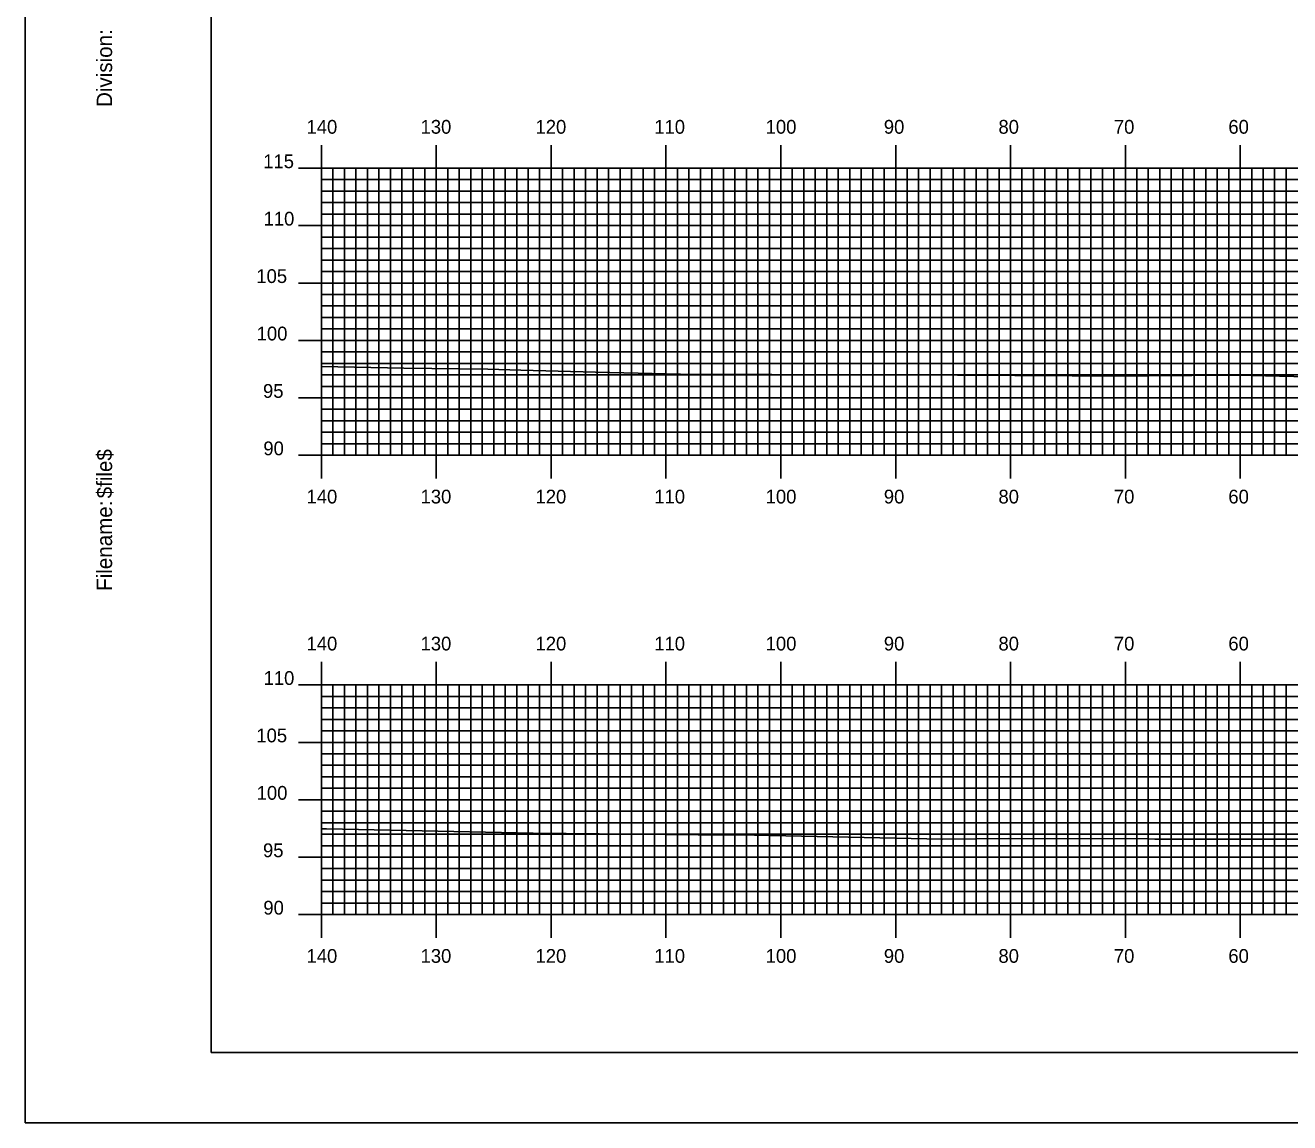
# Model space of a CAD drawing. Extents: x 1764939 to 1765282, y 442591 to 442811.
# Drawn here: x 1764939.1 to 1765049.2, y 442590.5 to 442686.1 of the extents above; entities that cross this region are included whole.
import ezdxf

# ---------------------------------------------------------------- set-up
doc = ezdxf.new("R2010")
doc.units = 0
for name, color, linetype in [('BORDER', 7, 'Continuous'), ('H_V ANNOTATION', 7, 'Continuous'), ('MAJOR', 7, 'Continuous'), ('MINOR', 7, 'Continuous'), ('PLOT BOUNDARY', 7, 'Continuous'), ('S_Roadway_Centerline', 7, 'Continuous')]:
    doc.layers.add(name, color=color, linetype=linetype)

msp = doc.modelspace()

# ---------------------------------------------------------------- linework, layer by layer
at = {"layer": 'BORDER'}
msp.add_lwpolyline([(1764955.26, 442596.67), (1765275.26, 442596.67), (1765275.26, 442806.67), (1764955.26, 442806.67)], close=True, dxfattribs=at)
at = {"layer": 'MAJOR'}
for p, q in [((1764964.86, 442675.67), (1764964.86, 442673.67)), ((1764974.86, 442675.67), (1764974.86, 442673.67)), ((1764984.86, 442675.67), (1764984.86, 442673.67)), ((1764994.86, 442675.67), (1764994.86, 442673.67)), ((1765004.86, 442675.67), (1765004.86, 442673.67)), ((1765014.86, 442675.67), (1765014.86, 442673.67)), ((1765024.86, 442675.67), (1765024.86, 442673.67)), ((1765034.86, 442675.67), (1765034.86, 442673.67)), ((1765044.86, 442675.67), (1765044.86, 442673.67)), ((1764962.85, 442673.67), (1764964.86, 442673.67)), ((1764964.86, 442673.67), (1765244.86, 442673.67)), ((1764964.86, 442648.67), (1764964.86, 442673.67)), ((1764964.86, 442648.67), (1764964.86, 442673.67)), ((1764964.86, 442673.67), (1765244.86, 442673.67)), ((1764974.86, 442648.67), (1764974.86, 442673.67)), ((1764984.86, 442648.67), (1764984.86, 442673.67)), ((1764994.86, 442648.67), (1764994.86, 442673.67)), ((1765004.86, 442648.67), (1765004.86, 442673.67)), ((1765014.86, 442648.67), (1765014.86, 442673.67)), ((1765024.86, 442648.67), (1765024.86, 442673.67)), ((1765034.86, 442648.67), (1765034.86, 442673.67)), ((1765044.86, 442648.67), (1765044.86, 442673.67)), ((1764962.85, 442668.67), (1764964.86, 442668.67)), ((1764964.86, 442668.67), (1765244.86, 442668.67)), ((1764962.85, 442663.67), (1764964.86, 442663.67)), ((1764964.86, 442663.67), (1765244.86, 442663.67)), ((1764962.85, 442658.67), (1764964.86, 442658.67)), ((1764964.86, 442658.67), (1765244.86, 442658.67)), ((1764962.85, 442653.67), (1764964.86, 442653.67)), ((1764964.86, 442653.67), (1765244.86, 442653.67)), ((1764962.85, 442648.67), (1764964.86, 442648.67)), ((1764964.86, 442648.67), (1765244.86, 442648.67)), ((1764964.86, 442648.67), (1765244.86, 442648.67)), ((1764964.86, 442646.66), (1764964.86, 442648.67)), ((1764974.86, 442646.66), (1764974.86, 442648.67)), ((1764984.86, 442646.66), (1764984.86, 442648.67)), ((1764994.86, 442646.66), (1764994.86, 442648.67)), ((1765004.86, 442646.66), (1765004.86, 442648.67)), ((1765014.86, 442646.66), (1765014.86, 442648.67)), ((1765024.86, 442646.66), (1765024.86, 442648.67)), ((1765034.86, 442646.66), (1765034.86, 442648.67)), ((1765044.86, 442646.66), (1765044.86, 442648.67)), ((1764964.86, 442630.67), (1764964.86, 442628.67)), ((1764974.86, 442630.67), (1764974.86, 442628.67)), ((1764984.86, 442630.67), (1764984.86, 442628.67)), ((1764994.86, 442630.67), (1764994.86, 442628.67)), ((1765004.86, 442630.67), (1765004.86, 442628.67)), ((1765014.86, 442630.67), (1765014.86, 442628.67)), ((1765024.86, 442630.67), (1765024.86, 442628.67)), ((1765034.86, 442630.67), (1765034.86, 442628.67)), ((1765044.86, 442630.67), (1765044.86, 442628.67)), ((1764962.85, 442628.67), (1764964.86, 442628.67)), ((1764964.86, 442628.67), (1765244.86, 442628.67)), ((1764964.86, 442608.67), (1764964.86, 442628.67)), ((1764964.86, 442608.67), (1764964.86, 442628.67)), ((1764964.86, 442628.67), (1765244.86, 442628.67)), ((1764974.86, 442608.67), (1764974.86, 442628.67)), ((1764984.86, 442608.67), (1764984.86, 442628.67)), ((1764994.86, 442608.67), (1764994.86, 442628.67)), ((1765004.86, 442608.67), (1765004.86, 442628.67)), ((1765014.86, 442608.67), (1765014.86, 442628.67)), ((1765024.86, 442608.67), (1765024.86, 442628.67)), ((1765034.86, 442608.67), (1765034.86, 442628.67)), ((1765044.86, 442608.67), (1765044.86, 442628.67)), ((1764962.85, 442623.67), (1764964.86, 442623.67)), ((1764964.86, 442623.67), (1765244.86, 442623.67)), ((1764962.85, 442618.67), (1764964.86, 442618.67)), ((1764964.86, 442618.67), (1765244.86, 442618.67)), ((1764962.85, 442613.67), (1764964.86, 442613.67)), ((1764964.86, 442613.67), (1765244.86, 442613.67)), ((1764962.85, 442608.67), (1764964.86, 442608.67)), ((1764964.86, 442608.67), (1765244.86, 442608.67)), ((1764964.86, 442608.67), (1765244.86, 442608.67)), ((1764964.86, 442606.66), (1764964.86, 442608.67)), ((1764974.86, 442606.66), (1764974.86, 442608.67)), ((1764984.86, 442606.66), (1764984.86, 442608.67)), ((1764994.86, 442606.66), (1764994.86, 442608.67)), ((1765004.86, 442606.66), (1765004.86, 442608.67)), ((1765014.86, 442606.66), (1765014.86, 442608.67)), ((1765024.86, 442606.66), (1765024.86, 442608.67)), ((1765034.86, 442606.66), (1765034.86, 442608.67)), ((1765044.86, 442606.66), (1765044.86, 442608.67))]:
    msp.add_line(p, q, dxfattribs=at)
at = {"layer": 'MINOR'}
for p, q in [((1764964.86, 442672.67), (1765244.86, 442672.67)), ((1764964.86, 442672.67), (1764966.86, 442672.67)), ((1764965.86, 442648.67), (1764965.86, 442673.67)), ((1764966.86, 442648.67), (1764966.86, 442673.67)), ((1764967.86, 442648.67), (1764967.86, 442673.67)), ((1764968.86, 442648.67), (1764968.86, 442673.67)), ((1764969.86, 442648.67), (1764969.86, 442673.67)), ((1764970.86, 442648.67), (1764970.86, 442673.67)), ((1764971.86, 442648.67), (1764971.86, 442673.67)), ((1764972.86, 442648.67), (1764972.86, 442673.67)), ((1764973.86, 442648.67), (1764973.86, 442673.67)), ((1764975.86, 442648.67), (1764975.86, 442673.67)), ((1764976.86, 442648.67), (1764976.86, 442673.67)), ((1764977.86, 442648.67), (1764977.86, 442673.67)), ((1764978.86, 442648.67), (1764978.86, 442673.67)), ((1764979.86, 442648.67), (1764979.86, 442673.67)), ((1764980.86, 442648.67), (1764980.86, 442673.67)), ((1764981.86, 442648.67), (1764981.86, 442673.67)), ((1764982.86, 442648.67), (1764982.86, 442673.67)), ((1764983.86, 442648.67), (1764983.86, 442673.67)), ((1764985.86, 442648.67), (1764985.86, 442673.67)), ((1764986.86, 442648.67), (1764986.86, 442673.67)), ((1764987.86, 442648.67), (1764987.86, 442673.67)), ((1764988.86, 442648.67), (1764988.86, 442673.67)), ((1764989.86, 442648.67), (1764989.86, 442673.67)), ((1764990.86, 442648.67), (1764990.86, 442673.67)), ((1764991.86, 442648.67), (1764991.86, 442673.67)), ((1764992.86, 442648.67), (1764992.86, 442673.67)), ((1764993.86, 442648.67), (1764993.86, 442673.67)), ((1764995.86, 442648.67), (1764995.86, 442673.67)), ((1764996.86, 442648.67), (1764996.86, 442673.67)), ((1764997.86, 442648.67), (1764997.86, 442673.67)), ((1764998.86, 442648.67), (1764998.86, 442673.67)), ((1764999.86, 442648.67), (1764999.86, 442673.67)), ((1765000.86, 442648.67), (1765000.86, 442673.67)), ((1765001.86, 442648.67), (1765001.86, 442673.67)), ((1765002.86, 442648.67), (1765002.86, 442673.67)), ((1765003.86, 442648.67), (1765003.86, 442673.67)), ((1765005.86, 442648.67), (1765005.86, 442673.67)), ((1765006.86, 442648.67), (1765006.86, 442673.67)), ((1765007.86, 442648.67), (1765007.86, 442673.67)), ((1765008.86, 442648.67), (1765008.86, 442673.67)), ((1765009.86, 442648.67), (1765009.86, 442673.67)), ((1765010.86, 442648.67), (1765010.86, 442673.67)), ((1765011.86, 442648.67), (1765011.86, 442673.67)), ((1765012.86, 442648.67), (1765012.86, 442673.67)), ((1765013.86, 442648.67), (1765013.86, 442673.67)), ((1765015.86, 442648.67), (1765015.86, 442673.67)), ((1765016.86, 442648.67), (1765016.86, 442673.67)), ((1765017.86, 442648.67), (1765017.86, 442673.67)), ((1765018.86, 442648.67), (1765018.86, 442673.67)), ((1765019.86, 442648.67), (1765019.86, 442673.67)), ((1765020.86, 442648.67), (1765020.86, 442673.67)), ((1765021.86, 442648.67), (1765021.86, 442673.67)), ((1765022.86, 442648.67), (1765022.86, 442673.67)), ((1765023.86, 442648.67), (1765023.86, 442673.67)), ((1765025.86, 442648.67), (1765025.86, 442673.67)), ((1765026.86, 442648.67), (1765026.86, 442673.67)), ((1765027.86, 442648.67), (1765027.86, 442673.67)), ((1765028.86, 442648.67), (1765028.86, 442673.67)), ((1765029.86, 442648.67), (1765029.86, 442673.67)), ((1765030.86, 442648.67), (1765030.86, 442673.67)), ((1765031.86, 442648.67), (1765031.86, 442673.67)), ((1765032.86, 442648.67), (1765032.86, 442673.67)), ((1765033.86, 442648.67), (1765033.86, 442673.67)), ((1765035.86, 442648.67), (1765035.86, 442673.67)), ((1765036.86, 442648.67), (1765036.86, 442673.67)), ((1765037.86, 442648.67), (1765037.86, 442673.67)), ((1765038.86, 442648.67), (1765038.86, 442673.67)), ((1765039.86, 442648.67), (1765039.86, 442673.67)), ((1765040.86, 442648.67), (1765040.86, 442673.67)), ((1765041.86, 442648.67), (1765041.86, 442673.67)), ((1765042.86, 442648.67), (1765042.86, 442673.67)), ((1765043.86, 442648.67), (1765043.86, 442673.67)), ((1765045.86, 442648.67), (1765045.86, 442673.67)), ((1765046.86, 442648.67), (1765046.86, 442673.67)), ((1765047.86, 442648.67), (1765047.86, 442673.67)), ((1765048.86, 442648.67), (1765048.86, 442673.67)), ((1764964.86, 442671.67), (1765244.86, 442671.67)), ((1764964.86, 442671.67), (1764966.86, 442671.67)), ((1764964.86, 442670.67), (1765244.86, 442670.67)), ((1764964.86, 442670.67), (1764966.86, 442670.67)), ((1764964.86, 442669.67), (1765244.86, 442669.67)), ((1764964.86, 442669.67), (1764966.86, 442669.67)), ((1764964.86, 442667.67), (1765244.86, 442667.67)), ((1764964.86, 442667.67), (1764966.86, 442667.67)), ((1764964.86, 442666.67), (1765244.86, 442666.67)), ((1764964.86, 442666.67), (1764966.86, 442666.67)), ((1764964.86, 442665.67), (1765244.86, 442665.67)), ((1764964.86, 442665.67), (1764966.86, 442665.67)), ((1764964.86, 442664.67), (1765244.86, 442664.67)), ((1764964.86, 442664.67), (1764966.86, 442664.67)), ((1764964.86, 442662.67), (1765244.86, 442662.67)), ((1764964.86, 442662.67), (1764966.86, 442662.67)), ((1764964.86, 442661.67), (1765244.86, 442661.67)), ((1764964.86, 442661.67), (1764966.86, 442661.67)), ((1764964.86, 442660.67), (1765244.86, 442660.67)), ((1764964.86, 442660.67), (1764966.86, 442660.67)), ((1764964.86, 442659.67), (1765244.86, 442659.67)), ((1764964.86, 442659.67), (1764966.86, 442659.67)), ((1764964.86, 442657.67), (1765244.86, 442657.67)), ((1764964.86, 442657.67), (1764966.86, 442657.67)), ((1764964.86, 442656.67), (1765244.86, 442656.67)), ((1764964.86, 442656.67), (1764966.86, 442656.67)), ((1764964.86, 442655.67), (1765244.86, 442655.67)), ((1764964.86, 442655.67), (1764966.86, 442655.67)), ((1764964.86, 442654.67), (1765244.86, 442654.67)), ((1764964.86, 442654.67), (1764966.86, 442654.67)), ((1764964.86, 442652.67), (1765244.86, 442652.67)), ((1764964.86, 442652.67), (1764966.86, 442652.67)), ((1764964.86, 442651.67), (1765244.86, 442651.67)), ((1764964.86, 442651.67), (1764966.86, 442651.67)), ((1764964.86, 442650.67), (1765244.86, 442650.67)), ((1764964.86, 442650.67), (1764966.86, 442650.67)), ((1764964.86, 442649.67), (1765244.86, 442649.67)), ((1764964.86, 442649.67), (1764966.86, 442649.67)), ((1764965.86, 442608.67), (1764965.86, 442628.67)), ((1764966.86, 442608.67), (1764966.86, 442628.67)), ((1764967.86, 442608.67), (1764967.86, 442628.67)), ((1764968.86, 442608.67), (1764968.86, 442628.67)), ((1764969.86, 442608.67), (1764969.86, 442628.67)), ((1764970.86, 442608.67), (1764970.86, 442628.67)), ((1764971.86, 442608.67), (1764971.86, 442628.67)), ((1764972.86, 442608.67), (1764972.86, 442628.67)), ((1764973.86, 442608.67), (1764973.86, 442628.67)), ((1764975.86, 442608.67), (1764975.86, 442628.67)), ((1764976.86, 442608.67), (1764976.86, 442628.67)), ((1764977.86, 442608.67), (1764977.86, 442628.67)), ((1764978.86, 442608.67), (1764978.86, 442628.67)), ((1764979.86, 442608.67), (1764979.86, 442628.67)), ((1764980.86, 442608.67), (1764980.86, 442628.67)), ((1764981.86, 442608.67), (1764981.86, 442628.67)), ((1764982.86, 442608.67), (1764982.86, 442628.67)), ((1764983.86, 442608.67), (1764983.86, 442628.67)), ((1764985.86, 442608.67), (1764985.86, 442628.67)), ((1764986.86, 442608.67), (1764986.86, 442628.67)), ((1764987.86, 442608.67), (1764987.86, 442628.67)), ((1764988.86, 442608.67), (1764988.86, 442628.67)), ((1764989.86, 442608.67), (1764989.86, 442628.67)), ((1764990.86, 442608.67), (1764990.86, 442628.67)), ((1764991.86, 442608.67), (1764991.86, 442628.67)), ((1764992.86, 442608.67), (1764992.86, 442628.67)), ((1764993.86, 442608.67), (1764993.86, 442628.67)), ((1764995.86, 442608.67), (1764995.86, 442628.67)), ((1764996.86, 442608.67), (1764996.86, 442628.67)), ((1764997.86, 442608.67), (1764997.86, 442628.67)), ((1764998.86, 442608.67), (1764998.86, 442628.67)), ((1764999.86, 442608.67), (1764999.86, 442628.67)), ((1765000.86, 442608.67), (1765000.86, 442628.67)), ((1765001.86, 442608.67), (1765001.86, 442628.67)), ((1765002.86, 442608.67), (1765002.86, 442628.67)), ((1765003.86, 442608.67), (1765003.86, 442628.67)), ((1765005.86, 442608.67), (1765005.86, 442628.67)), ((1765006.86, 442608.67), (1765006.86, 442628.67)), ((1765007.86, 442608.67), (1765007.86, 442628.67)), ((1765008.86, 442608.67), (1765008.86, 442628.67)), ((1765009.86, 442608.67), (1765009.86, 442628.67)), ((1765010.86, 442608.67), (1765010.86, 442628.67)), ((1765011.86, 442608.67), (1765011.86, 442628.67)), ((1765012.86, 442608.67), (1765012.86, 442628.67)), ((1765013.86, 442608.67), (1765013.86, 442628.67)), ((1765015.86, 442608.67), (1765015.86, 442628.67)), ((1765016.86, 442608.67), (1765016.86, 442628.67)), ((1765017.86, 442608.67), (1765017.86, 442628.67)), ((1765018.86, 442608.67), (1765018.86, 442628.67)), ((1765019.86, 442608.67), (1765019.86, 442628.67)), ((1765020.86, 442608.67), (1765020.86, 442628.67)), ((1765021.86, 442608.67), (1765021.86, 442628.67)), ((1765022.86, 442608.67), (1765022.86, 442628.67)), ((1765023.86, 442608.67), (1765023.86, 442628.67)), ((1765025.86, 442608.67), (1765025.86, 442628.67)), ((1765026.86, 442608.67), (1765026.86, 442628.67)), ((1765027.86, 442608.67), (1765027.86, 442628.67)), ((1765028.86, 442608.67), (1765028.86, 442628.67)), ((1765029.86, 442608.67), (1765029.86, 442628.67)), ((1765030.86, 442608.67), (1765030.86, 442628.67)), ((1765031.86, 442608.67), (1765031.86, 442628.67)), ((1765032.86, 442608.67), (1765032.86, 442628.67)), ((1765033.86, 442608.67), (1765033.86, 442628.67)), ((1765035.86, 442608.67), (1765035.86, 442628.67)), ((1765036.86, 442608.67), (1765036.86, 442628.67)), ((1765037.86, 442608.67), (1765037.86, 442628.67)), ((1765038.86, 442608.67), (1765038.86, 442628.67)), ((1765039.86, 442608.67), (1765039.86, 442628.67)), ((1765040.86, 442608.67), (1765040.86, 442628.67)), ((1765041.86, 442608.67), (1765041.86, 442628.67)), ((1765042.86, 442608.67), (1765042.86, 442628.67)), ((1765043.86, 442608.67), (1765043.86, 442628.67)), ((1765045.86, 442608.67), (1765045.86, 442628.67)), ((1765046.86, 442608.67), (1765046.86, 442628.67)), ((1765047.86, 442608.67), (1765047.86, 442628.67)), ((1765048.86, 442608.67), (1765048.86, 442628.67)), ((1764964.86, 442627.67), (1765244.86, 442627.67)), ((1764964.86, 442627.67), (1764966.86, 442627.67)), ((1764964.86, 442626.67), (1765244.86, 442626.67)), ((1764964.86, 442626.67), (1764966.86, 442626.67)), ((1764964.86, 442625.67), (1765244.86, 442625.67)), ((1764964.86, 442625.67), (1764966.86, 442625.67)), ((1764964.86, 442624.67), (1765244.86, 442624.67)), ((1764964.86, 442624.67), (1764966.86, 442624.67)), ((1764964.86, 442622.67), (1765244.86, 442622.67)), ((1764964.86, 442622.67), (1764966.86, 442622.67)), ((1764964.86, 442621.67), (1765244.86, 442621.67)), ((1764964.86, 442621.67), (1764966.86, 442621.67)), ((1764964.86, 442620.67), (1765244.86, 442620.67)), ((1764964.86, 442620.67), (1764966.86, 442620.67)), ((1764964.86, 442619.67), (1765244.86, 442619.67)), ((1764964.86, 442619.67), (1764966.86, 442619.67)), ((1764964.86, 442617.67), (1765244.86, 442617.67)), ((1764964.86, 442617.67), (1764966.86, 442617.67)), ((1764964.86, 442616.67), (1765244.86, 442616.67)), ((1764964.86, 442616.67), (1764966.86, 442616.67)), ((1764964.86, 442615.67), (1765244.86, 442615.67)), ((1764964.86, 442615.67), (1764966.86, 442615.67)), ((1764964.86, 442614.67), (1765244.86, 442614.67)), ((1764964.86, 442614.67), (1764966.86, 442614.67)), ((1764964.86, 442612.67), (1765244.86, 442612.67)), ((1764964.86, 442612.67), (1764966.86, 442612.67)), ((1764964.86, 442611.67), (1765244.86, 442611.67)), ((1764964.86, 442611.67), (1764966.86, 442611.67)), ((1764964.86, 442610.67), (1765244.86, 442610.67)), ((1764964.86, 442610.67), (1764966.86, 442610.67)), ((1764964.86, 442609.67), (1765244.86, 442609.67)), ((1764964.86, 442609.67), (1764966.86, 442609.67))]:
    msp.add_line(p, q, dxfattribs=at)
at = {"layer": 'PLOT BOUNDARY'}
msp.add_lwpolyline([(1764939.07, 442590.55), (1765279.07, 442590.55), (1765279.07, 442810.55), (1764939.07, 442810.55)], close=True, dxfattribs=at)
at = {"layer": 'S_Roadway_Centerline'}
for points in [[(1764964.86, 442656.39), (1764972.04, 442656.25), (1764979.36, 442656.18), (1764982.22, 442656.08), (1764988.72, 442655.9), (1764997.37, 442655.7), (1765004.08, 442655.69), (1765015.25, 442655.68), (1765030.24, 442655.58), (1765032.84, 442655.57), (1765044.58, 442655.65), (1765050.78, 442655.49)], [(1764964.86, 442616.14), (1764965.29, 442616.14), (1764972.23, 442615.99), (1764983.29, 442615.76), (1764997.66, 442615.63), (1765001.16, 442615.62), (1765003.92, 442615.57), (1765018.94, 442615.24), (1765024.69, 442615.31), (1765036.89, 442615.26), (1765037.43, 442615.25), (1765038.72, 442615.25), (1765055.02, 442615.24)]]:
    msp.add_lwpolyline(points, dxfattribs=at)

# ---------------------------------------------------------------- texts
at = {"layer": 'BORDER'}
for s, p in [('Division:', (1764946.63, 442679)), ('$file$', (1764946.63, 442644.92)), ('Filename:', (1764946.63, 442636.86))]:
    msp.add_text(s, height=1.339, rotation=90, dxfattribs=at).set_placement(p)
at = {"layer": 'H_V ANNOTATION'}
for s, p in [('140', (1764963.56, 442676.67)), ('130', (1764973.49, 442676.67)), ('120', (1764983.5, 442676.67)), ('110', (1764993.84, 442676.67)), ('100', (1765003.54, 442676.67)), ('90', (1765013.83, 442676.67)), ('80', (1765023.81, 442676.67)), ('70', (1765033.86, 442676.67)), ('60', (1765043.83, 442676.67)), ('115', (1764959.79, 442673.67)), ('110', (1764959.82, 442668.67)), ('105', (1764959.19, 442663.67)), ('100', (1764959.22, 442658.67)), ('95', (1764959.77, 442653.67)), ('90', (1764959.8, 442648.67)), ('140', (1764963.56, 442644.47)), ('130', (1764973.49, 442644.47)), ('120', (1764983.5, 442644.47)), ('110', (1764993.84, 442644.47)), ('100', (1765003.54, 442644.47)), ('90', (1765013.83, 442644.47)), ('80', (1765023.81, 442644.47)), ('70', (1765033.86, 442644.47)), ('60', (1765043.83, 442644.47)), ('140', (1764963.56, 442631.67)), ('130', (1764973.49, 442631.67)), ('120', (1764983.5, 442631.67)), ('110', (1764993.84, 442631.67)), ('100', (1765003.54, 442631.67)), ('90', (1765013.83, 442631.67)), ('80', (1765023.81, 442631.67)), ('70', (1765033.86, 442631.67)), ('60', (1765043.83, 442631.67)), ('110', (1764959.82, 442628.67)), ('105', (1764959.19, 442623.67)), ('100', (1764959.22, 442618.67)), ('95', (1764959.77, 442613.67)), ('90', (1764959.8, 442608.67)), ('140', (1764963.56, 442604.47)), ('130', (1764973.49, 442604.47)), ('120', (1764983.5, 442604.47)), ('110', (1764993.84, 442604.47)), ('100', (1765003.54, 442604.47)), ('90', (1765013.83, 442604.47)), ('80', (1765023.81, 442604.47)), ('70', (1765033.86, 442604.47)), ('60', (1765043.83, 442604.47))]:
    msp.add_text(s, height=1.2, dxfattribs=at).set_placement(p)
at = {"layer": 'MAJOR'}
for p in [(1764964.85, 442648.67), (1764964.85, 442608.67)]:
    msp.add_text('-', height=0.012, dxfattribs=at).set_placement(p)

doc.saveas('drawing.dxf')
